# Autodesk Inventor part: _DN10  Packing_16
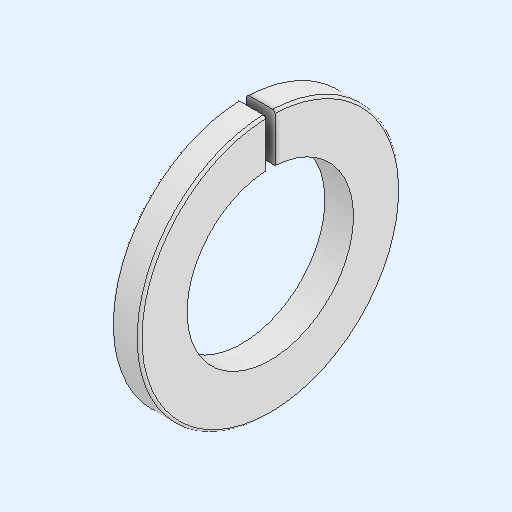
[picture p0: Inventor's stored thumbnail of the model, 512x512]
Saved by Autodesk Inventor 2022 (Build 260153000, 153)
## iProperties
Created: 2021-12
Part Number: _DN10  Packing_16
Material: Generico
Document SubType Name: Modeling
Designer: admin
Density: 1 g/cm^3
Appearance: Default
Author: admin
Revision Number: NONE
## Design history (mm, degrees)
feature "_DN10  Packing"
node "Solido1"
